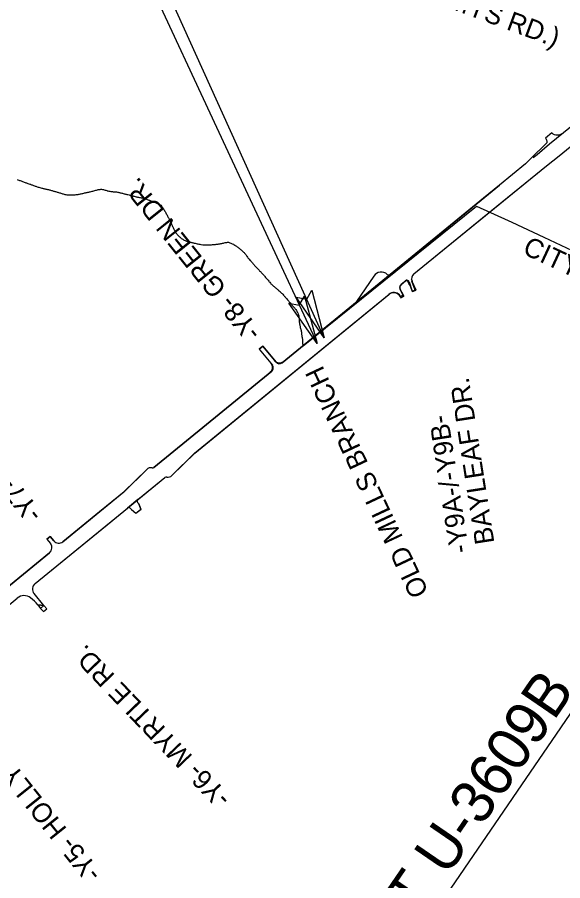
# Model space of a CAD drawing. Extents: x 2312641 to 2338852, y 590461 to 618614.
# Drawn here: x 2323527 to 2326066, y 598163 to 602179 of the extents above; entities that cross this region are included whole.
import ezdxf

# ---------------------------------------------------------------- set-up
doc = ezdxf.new("R2010")
doc.units = 0
for name, color, linetype in [('Default', 7, 'Continuous'), ('Default Symbol CELL', 7, 'Continuous'), ('Exist Property Monument CELL', 7, 'Continuous'), ('Exist Structure Minor Head and End Wall Leader', 7, 'Continuous'), ('Exist Structure Minor Pipes RCP 15 Inch Text', 7, 'Continuous')]:
    doc.layers.add(name, color=color, linetype=linetype)

msp = doc.modelspace()

# ---------------------------------------------------------------- linework, layer by layer
at = {"layer": 'Default'}
for points in [[(2323526.2, 601424.9), (2323530, 601423.4), (2323534, 601421.8), (2323537.8, 601420.4), (2323541, 601419.1), (2323544.8, 601417.6), (2323548.5, 601416.2), (2323552, 601414.9), (2323556, 601413.4), (2323559.8, 601412.1), (2323563.5, 601410.7), (2323567.2, 601409.3), (2323570.2, 601408.3), (2323573, 601407.3), (2323576.8, 601405.9), (2323580.5, 601404.6), (2323584.8, 601403.1), (2323588, 601401.9), (2323591, 601400.9), (2323593.8, 601399.9), (2323596.5, 601398.9), (2323599.5, 601397.8), (2323602.2, 601396.8), (2323607, 601395.2), (2323610.8, 601393.9), (2323613.5, 601392.9), (2323616.5, 601391.9), (2323619.5, 601390.9), (2323624, 601389.4), (2323627.8, 601388.2), (2323631.8, 601387.1), (2323636.2, 601385.8), (2323641.2, 601384.4), (2323644.2, 601383.7), (2323647, 601382.9), (2323650, 601382.2), (2323653.8, 601381.2), (2323656.8, 601380.6), (2323660.8, 601379.8), (2323664.5, 601378.9), (2323668, 601378.2), (2323672, 601377.3), (2323675.2, 601376.5), (2323678.2, 601375.8), (2323682.2, 601374.9), (2323686, 601373.9), (2323689, 601372.9), (2323692.8, 601371.8), (2323695.5, 601370.8), (2323699.2, 601369.6), (2323702.2, 601368.8), (2323705.5, 601367.8), (2323709, 601366.8), (2323712.8, 601365.8), (2323716.5, 601364.7), (2323719.5, 601363.8), (2323723.2, 601362.6), (2323726.2, 601361.7), (2323730, 601360.4), (2323733.8, 601359.2), (2323737.5, 601357.9), (2323740.5, 601357), (2323745.2, 601355.9), (2323749.2, 601355.1), (2323753, 601354.3), (2323757.5, 601353.6), (2323760.5, 601353.3), (2323765, 601353), (2323768, 601352.8), (2323769.5, 601352.6), (2323773, 601352.7), (2323777.5, 601352.5), (2323780.5, 601352.6), (2323785, 601352.9)], [(2323785, 601352.9), (2323789, 601353.1), (2323793, 601353.4), (2323796.2, 601353.6), (2323801, 601354.2), (2323810, 601355.3), (2323813.5, 601355.9), (2323816.8, 601356.4), (2323820.8, 601357.2), (2323824.5, 601358.1), (2323828.5, 601358.9), (2323831.5, 601359.6), (2323836.2, 601360.8), (2323840.2, 601361.6), (2323844, 601362.6), (2323848.5, 601363.6), (2323852, 601364.2), (2323856, 601364.9), (2323859.8, 601365.7), (2323863.8, 601366.4), (2323867, 601367.1), (2323871.5, 601368.4), (2323875.2, 601369.4), (2323879.2, 601370.6), (2323883.5, 601371.8), (2323888.8, 601373.3), (2323892.8, 601374.4), (2323896.5, 601375.4), (2323901, 601376.6), (2323904.2, 601377.2), (2323908.2, 601377.9), (2323912.2, 601378.5), (2323916.2, 601379), (2323919.2, 601379.2), (2323924, 601378.3), (2323928, 601377.4), (2323931.8, 601376.4), (2323936.5, 601375.1), (2323939.5, 601374.1), (2323943.2, 601373), (2323946.2, 601372.2), (2323949, 601371.4), (2323953.8, 601370.3), (2323958.5, 601369.6), (2323962.2, 601369), (2323966.2, 601368.5), (2323970.8, 601367.9), (2323974.2, 601367.7), (2323982.2, 601367.2), (2323986.2, 601366.8), (2323989.2, 601366.5), (2323993.2, 601365.8), (2323996, 601365.2), (2324000, 601364.4), (2324003, 601363.7), (2324006.2, 601362.9), (2324009.8, 601362), (2324013.5, 601361), (2324016.5, 601360.2), (2324019.2, 601359.4), (2324024, 601358.2), (2324028, 601357.2), (2324031, 601356.5), (2324034, 601355.8), (2324036.8, 601355), (2324041.5, 601353.8), (2324047.5, 601352.3), (2324051.2, 601351.3), (2324054.2, 601350.6), (2324058.5, 601349.5), (2324062, 601348.7), (2324066, 601347.7), (2324068.8, 601347), (2324071.8, 601346.3), (2324076, 601345.2), (2324080, 601344.4), (2324083.5, 601343.6), (2324087.2, 601342.8), (2324091.2, 601341.9), (2324095.5, 601341), (2324099, 601340.2), (2324103, 601339.3), (2324106.8, 601338.4), (2324111.2, 601337.4), (2324116.5, 601336.1), (2324120.5, 601335), (2324124.2, 601333.9), (2324128.8, 601332.7), (2324132, 601331.6), (2324135.8, 601330.1), (2324139.2, 601328.7), (2324142.2, 601327.5), (2324145.8, 601326.1), (2324148.5, 601324.9), (2324152.2, 601323.5), (2324156, 601322.1), (2324159, 601321.2)], [(2324159, 601321.2), (2324162.8, 601320), (2324165.5, 601319), (2324169.2, 601317.5), (2324173, 601316.1), (2324175.8, 601314.9), (2324178, 601314.1), (2324182.2, 601311.9), (2324185.8, 601310), (2324189, 601308.7), (2324190.2, 601307.5), (2324194.8, 601304.3), (2324198.2, 601300.5), (2324200.8, 601297.4), (2324203.2, 601294.3), (2324205.8, 601290.7), (2324208.2, 601286.6), (2324210.8, 601282.5), (2324212.8, 601279.1), (2324215, 601275.2), (2324216.8, 601272.1), (2324218.5, 601268.6), (2324220.5, 601265.1), (2324222.8, 601260.8), (2324224.2, 601258), (2324226, 601254.4), (2324227.8, 601250.9), (2324230, 601247.5), (2324232.2, 601243.8), (2324234.8, 601238.8), (2324236.8, 601235.2), (2324239.2, 601230), (2324241, 601226.8), (2324242.2, 601224), (2324243.5, 601220.9), (2324245.2, 601217.2), (2324247, 601212.8), (2324248.2, 601209.9), (2324250, 601206.2), (2324251.2, 601203.4), (2324252.2, 601200.7), (2324254, 601197.1), (2324255.5, 601193.8), (2324257, 601190.7), (2324258.2, 601187.9), (2324260, 601184.4), (2324261.8, 601180.8), (2324263.2, 601178), (2324266.2, 601174.3), (2324269, 601171.3), (2324271.8, 601168.4), (2324274.2, 601165.6), (2324277, 601162.7), (2324279.2, 601160.4), (2324281.5, 601158.3), (2324284.5, 601155.6), (2324287.8, 601152.3), (2324290.5, 601150.4), (2324293.8, 601148.2), (2324297.2, 601146.1), (2324300.5, 601144), (2324303.5, 601142.4), (2324307.8, 601140.7), (2324311.5, 601139.3), (2324315.2, 601138.1), (2324319.5, 601136.7), (2324323, 601135.6), (2324326.8, 601134.5), (2324329.8, 601133.6), (2324334.5, 601132.2), (2324337.5, 601131.4), (2324340.5, 601130.8), (2324344.2, 601130.1), (2324347.2, 601129.4), (2324350, 601128.8), (2324355.8, 601127.6), (2324359.8, 601126.4), (2324363.8, 601125.4), (2324367.5, 601124.4), (2324372.2, 601123.4), (2324377.5, 601122.8), (2324381.2, 601122.3), (2324390.2, 601121.2), (2324393.2, 601120.9), (2324405.2, 601120.2), (2324408.2, 601120.1), (2324413.2, 601120.2), (2324417.2, 601120.4), (2324420.2, 601120.6), (2324424, 601120.8), (2324427, 601120.9), (2324431.2, 601121.2), (2324435.2, 601121.5), (2324438.2, 601121.8), (2324441.2, 601121.9), (2324444.8, 601122.2), (2324449.2, 601122.7)], [(2324752.5, 600900.8), (2324754.5, 600898.8), (2324757.2, 600896.2), (2324759.8, 600893.9), (2324762.8, 600890.4), (2324766, 600886.8), (2324769.5, 600882.9), (2324771.5, 600880.6), (2324773.2, 600878.4), (2324776, 600875.4), (2324778.5, 600872.4), (2324781.8, 600868.8), (2324784.8, 600865.4), (2324787.8, 600861.9), (2324790.5, 600858.8), (2324793, 600855.8), (2324795.8, 600852.4), (2324797.8, 600850), (2324800.5, 600846.4), (2324803, 600843.2), (2324805.2, 600840.1), (2324807.2, 600837.6), (2324810.2, 600834.7), (2324813.2, 600831.9), (2324816, 600829.1), (2324818.5, 600826.6), (2324821.2, 600823.2), (2324823.8, 600820), (2324826.8, 600815.4), (2324828.8, 600811.4), (2324830.5, 600807.9), (2324832.2, 600804.2), (2324834.5, 600798.6), (2324835.8, 600794.8), (2324837, 600790.2), (2324837.8, 600787.1), (2324838.2, 600783.2), (2324838.8, 600778), (2324839, 600773.2), (2324839, 600769.2), (2324839.2, 600765.2), (2324839.5, 600761.8), (2324840.2, 600757.3), (2324841, 600753.4), (2324842, 600749), (2324842.5, 600745.6), (2324843.2, 600742.6), (2324843.8, 600739.6), (2324844.5, 600735.5), (2324845.5, 600732), (2324846.5, 600729), (2324847.5, 600726.2), (2324848.8, 600721.8), (2324849, 600718.4), (2324849.5, 600713.6), (2324849.8, 600710.4), (2324850, 600706.9), (2324850.5, 600704), (2324850.8, 600700.5), (2324851.2, 600696.5), (2324851.8, 600693.6), (2324852.8, 600689.7), (2324853.2, 600686.8), (2324854, 600683.8), (2324854.8, 600680.1), (2324854.8, 600676.9), (2324854.5, 600672.9), (2324854.5, 600668.9), (2324854.2, 600665.4), (2324855, 600661), (2324855.5, 600657.3), (2324857, 600654.8), (2324858.5, 600651.2), (2325664.2, 601300), (2325730.2, 601270.9), (2325828.2, 601225.3), (2325978.2, 601155.4), (2326135.5, 601082.1)], [(2324449.2, 601122.7), (2324453.2, 601123.1), (2324457.2, 601123.5), (2324461.8, 601124.1)], [(2324461.8, 601124.1), (2324465, 601124.6), (2324468, 601125), (2324471, 601125.5), (2324475, 601126.2), (2324479.5, 601127), (2324482.8, 601127.8), (2324486.8, 601128.8), (2324490.5, 601129.8), (2324494.5, 601130.7), (2324497.8, 601131.5), (2324502.2, 601131.7), (2324505.8, 601132.2), (2324510, 601133), (2324514, 601131), (2324516.8, 601130.4), (2324521.2, 601128.4), (2324524.8, 601126.8), (2324527.8, 601125.6), (2324533, 601123.1), (2324535.5, 601121.4), (2324539, 601119.2), (2324541.5, 601117.6), (2324544, 601115.9), (2324547.5, 601113.5), (2324550.5, 601111.4), (2324553.8, 601109.1), (2324557, 601106.7), (2324559.2, 601104.9), (2324562.8, 601102.3), (2324566.2, 601099.2), (2324568.5, 601097.2), (2324570.8, 601095.2), (2324573.8, 601092.6), (2324576, 601090.6), (2324579.5, 601087.1), (2324582.5, 601084.2), (2324584.2, 601081.9), (2324587, 601080), (2324589.2, 601077.7), (2324591.2, 601074.8), (2324592.8, 601072.2), (2324594.2, 601069.6), (2324596, 601067), (2324598.5, 601062.8), (2324600.5, 601060.5), (2324603, 601057.5), (2324606, 601054), (2324610, 601049.6), (2324612.2, 601046.9), (2324614.2, 601044.7), (2324616.2, 601042.4), (2324618.8, 601039.3), (2324621.5, 601036.1), (2324624, 601033.2), (2324626.5, 601030.1), (2324629, 601027), (2324631.2, 601024.3), (2324633.2, 601022.1), (2324635.8, 601019.2), (2324639.8, 601015.1), (2324643, 601011.4), (2324646, 601008.4), (2324649.5, 601005), (2324652.2, 601002.2), (2324654.8, 600999.7), (2324658.5, 600996.1), (2324661.5, 600992.9), (2324664.2, 600990.1), (2324666.2, 600987.9), (2324668.8, 600985.2), (2324671.2, 600982.4), (2324674.2, 600979.1), (2324677, 600976.1), (2324679.8, 600973.1), (2324683.2, 600969.2), (2324686.2, 600965.6), (2324689, 600962.6), (2324691.5, 600959.6), (2324694.5, 600955.9), (2324697.8, 600951.8), (2324700.2, 600948.7), (2324702.2, 600946.5), (2324705.5, 600942), (2324708, 600939.4), (2324711, 600936.9), (2324714, 600934.2), (2324716.8, 600931.4), (2324719.2, 600929), (2324722.8, 600926), (2324725.8, 600923.4), (2324728.8, 600920.8), (2324731.8, 600918.2), (2324735, 600915.7), (2324738, 600913.2), (2324741.2, 600910.7), (2324743.5, 600908.8), (2324746.8, 600906.1), (2324750.2, 600902.8), (2324752.5, 600900.8)]]:
    msp.add_lwpolyline(points, dxfattribs=at)
at = {"layer": 'Default Symbol CELL'}
for p, q in [((2326003.7, 601589.6), (2326394.4, 601908.6)), ((2326048.6, 601534.6), (2326503.2, 601905.7)), ((2325946.4, 601541.2), (2326003.7, 601589.6)), ((2325927.6, 601525.9), (2325946.4, 601541.2)), ((2325989.7, 601488.2), (2326048.6, 601534.6)), ((2325373.5, 600985), (2325989.7, 601488.2)), ((2324759.5, 600572.2), (2325771.6, 601398.5)), ((2325312.2, 600935), (2325334.6, 600953.3)), ((2325350.4, 600948.9), (2325365.8, 600904.7)), ((2325379, 600909.3), (2325364.1, 600951.9)), ((2325308.4, 600916.4), (2325326.8, 600881.6)), ((2325365.8, 600904.7), (2325379, 600909.3)), ((2324352.9, 600151.9), (2325256.9, 600889.9)), ((2325310, 600879.1), (2325312.7, 600874.1)), ((2325312.7, 600874.1), (2325326.8, 600881.6)), ((2324653.6, 600635.2), (2324670.6, 600649.1)), ((2324653.6, 600635.2), (2324714.3, 600561.2)), ((2324670.6, 600649.1), (2324731.4, 600575)), ((2324163, 600085.2), (2324711.4, 600533)), ((2324247, 600047.8), (2324352.9, 600151.9)), ((2324130.1, 600076), (2324023.8, 599971.6)), ((2324088.9, 599936.3), (2324214.2, 600038.6)), ((2323739.4, 599739.4), (2324023.8, 599971.6)), ((2324087.2, 599922.6), (2324092.2, 599915.9)), ((2324092.2, 599915.9), (2324102.6, 599891.1)), ((2323609.9, 599545.3), (2324039.5, 599896)), ((2324052.7, 599895.6), (2324059.5, 599889.2)), ((2324059.5, 599889.2), (2324079.5, 599872.2)), ((2324079.2, 599872), (2324103.2, 599891.6)), ((2323665.4, 599751), (2323680.9, 599763.6)), ((2323665.4, 599751), (2323681.7, 599731)), ((2323680.9, 599763.6), (2323697.2, 599743.7)), ((2323030.9, 599161), (2323677.4, 599688.8)), ((2323651.3, 599442.6), (2323605.2, 599498.8)), ((2323622.2, 599446.5), (2323635.9, 599429.9)), ((2323651.3, 599442.6), (2323635.9, 599429.9))]:
    msp.add_line(p, q, dxfattribs=at)
for centre, radius, start, end in [((2325340.9, 600945.6), 10, 19.2579, 129.228), ((2325392.4, 600961.8), 30, 129.228, 199.2579), ((2325321.7, 600923.4), 15, 129.228, 207.8225), ((2325279.1, 600862.8), 35, 27.8225, 129.228), ((2324698.8, 600548.5), 20, 309.228, 39.3225), ((2324746.8, 600587.7), 20, 219.3225, 309.228), ((2324149, 600056.7), 27, 78.1586, 134.5091), ((2324156.6, 600093), 10, 258.1586, 309.228), ((2324220.5, 600030.8), 10, 78.1586, 129.228), ((2324228.1, 600067.1), 27, 258.1586, 314.5091), ((2324095.2, 599928.6), 10, 129.228, 216.809), ((2324045.8, 599888.3), 10, 46.993, 129.228), ((2323720.4, 599762.6), 30, 219.228, 309.228), ((2323658.4, 599712), 30, 309.228, 39.228), ((2323630.8, 599519.7), 33, 129.228, 219.3566), ((2323558.7, 599438.9), 50, 52.6181, 129.228), ((2323467.6, 599319.7), 200, 39.3566, 52.6181)]:
    msp.add_arc(centre, radius, start, end, dxfattribs=at)
at = {"layer": 'Exist Property Monument CELL'}
for p, q in [((2326048.6, 601534.6), (2326484.6, 601890.5)), ((2326014.5, 601641), (2325985.3, 601617.2)), ((2325990.1, 601592.9), (2325919.6, 601523.8)), ((2325985.3, 601617.2), (2325985.9, 601616.6)), ((2325919.6, 601523.8), (2325893, 601497.6)), ((2325989.7, 601488.2), (2326048.6, 601534.6)), ((2325734, 601279.4), (2325989.7, 601488.2)), ((2325696.5, 601337.2), (2324759.5, 600572.2)), ((2325373.5, 600985), (2325734, 601279.4)), ((2325104.6, 600854), (2325262.3, 600982.7)), ((2325186.6, 600975), (2325106.6, 600856.2)), ((2325314.6, 600937), (2325336.3, 600954.7)), ((2325334.6, 600953.3), (2325331.8, 600951)), ((2325336.3, 600954.7), (2325334.6, 600953.3)), ((2325338.6, 600955.8), (2325338.8, 600955.7)), ((2325338.8, 600955.7), (2325339.2, 600955.4)), ((2325341.2, 600953.9), (2325339.2, 600955.4)), ((2325343.3, 600951.8), (2325341.2, 600953.9)), ((2325363.8, 600955.7), (2325362.6, 600958.5)), ((2325364.1, 600951.9), (2325379, 600909.3)), ((2325379, 600909.3), (2325364.1, 600951.9)), ((2325383.5, 600909.9), (2325365.7, 600950.2)), ((2325309.6, 600912.2), (2325323.2, 600886.3)), ((2325323.2, 600886.3), (2325309.6, 600912.2)), ((2325365.7, 600904.7), (2325379, 600909.3)), ((2325379, 600909.3), (2325366.1, 600904.9)), ((2325367.2, 600902.7), (2325383.5, 600909.9)), ((2324352.7, 600151.7), (2325257.7, 600890.6)), ((2325257.7, 600890.6), (2325256.9, 600889.9)), ((2325305.4, 600887.4), (2325307.9, 600882.7)), ((2325307.9, 600882.7), (2325305.4, 600887.4)), ((2325310, 600879.1), (2325312.7, 600874.1)), ((2325323.2, 600886.3), (2325310.8, 600879.8)), ((2325310.8, 600879.8), (2325323.2, 600886.3)), ((2325312.7, 600874.1), (2325326.8, 600881.6)), ((2325326.8, 600881.6), (2325321.4, 600891.9)), ((2325366.1, 600904.9), (2325367.2, 600902.7)), ((2324670.6, 600649.1), (2324653.6, 600635.2)), ((2324653.6, 600635.2), (2324714.3, 600561.2)), ((2324731.4, 600575), (2324670.6, 600649.1)), ((2324714.3, 600561.2), (2324707.9, 600568.9)), ((2324725, 600582.8), (2324731.4, 600575)), ((2324759.5, 600572.2), (2324767.2, 600578.5)), ((2324711.4, 600533), (2324163, 600085.2)), ((2324703.7, 600526.7), (2324711.4, 600533)), ((2324247, 600047.8), (2324352.7, 600151.7)), ((2324130.1, 600076), (2324024.8, 599972.5)), ((2323945.2, 599819), (2324214.2, 600038.6)), ((2324024.1, 599971.9), (2323909.8, 599878.5)), ((2324088.9, 599936.3), (2324039.5, 599896)), ((2324092.2, 599915.9), (2324087.2, 599922.6)), ((2324102.6, 599891.1), (2324092.2, 599915.9)), ((2323909.8, 599878.5), (2323739.4, 599739.4)), ((2324052.7, 599895.6), (2324059.5, 599889.2)), ((2324059.5, 599889.2), (2324079.5, 599872.2)), ((2324079.5, 599872.2), (2324102.6, 599891.1)), ((2323609.9, 599545.3), (2323945.2, 599819)), ((2323680.9, 599763.6), (2323665.4, 599751)), ((2323665.4, 599751), (2323681.7, 599731)), ((2323697.2, 599743.7), (2323680.9, 599763.6)), ((2323677.4, 599688.8), (2323030.9, 599161)), ((2323178.7, 599193.2), (2323527, 599477.6)), ((2323651.3, 599442.6), (2323605.2, 599498.8)), ((2323651.3, 599442.6), (2323622.2, 599446.5)), ((2323622.2, 599446.5), (2323635.9, 599429.9)), ((2323622.2, 599446.5), (2323651.3, 599442.6)), ((2323635.9, 599429.9), (2323651.3, 599442.6)), ((2323651.3, 599442.6), (2323635.9, 599429.9)), ((2323635.9, 599429.9), (2323648.5, 599414.5)), ((2323648.5, 599414.5), (2323664, 599427.1)), ((2323664, 599427.1), (2323651.3, 599442.6))]:
    msp.add_line(p, q, dxfattribs=at)
for points in [[(2325893, 601497.6), (2325771.6, 601398.5), (2325696.5, 601337.2)], [(2325339.2, 600955.4), (2325338.8, 600955.7), (2325338.6, 600955.8)], [(2325339.2, 600955.4), (2325341.2, 600953.9), (2325343.3, 600951.8)], [(2325321.4, 600891.9), (2325311.1, 600910.8), (2325307.7, 600917.2)]]:
    msp.add_lwpolyline(points, dxfattribs=at)
for centre, radius, start, end in [((2326040.6, 601671.3), 40, 229.3066, 309.2278), ((2325961.5, 601595.8), 32, 10.9869, 40.323), ((2325983.1, 601600), 10, 314.4775, 10.9869), ((2325221.5, 600951.6), 42, 48.3568, 146.1555), ((2325256, 600990.5), 10, 228.3568, 309.228), ((2325338.1, 600943.3), 10, 58.5415, 129.228), ((2325340.9, 600945.6), 10, 100.1034, 129.228), ((2325340.9, 600945.6), 10, 100.1034, 129.228), ((2325339.5, 600950.8), 5, 99.7805, 129.228), ((2325339.5, 600950.8), 5, 28.0047, 129.228), ((2325339.5, 600950.8), 5, 70.0679, 99.7805), ((2325340.9, 600945.6), 10, 88.3688, 100.1034), ((2325340.9, 600945.6), 10, 88.3688, 100.1034), ((2325339.5, 600950.8), 5, 28.0047, 70.0679), ((2325338.1, 600943.3), 10, 40.6638, 58.5415), ((2324990.7, 600765.4), 400, 27.4527, 28.0047), ((2324990.7, 600765.4), 400, 20.3835, 28.0047), ((2325392.4, 600961.8), 30, 129.228, 199.2579), ((2325392.4, 600961.8), 30, 186.3702, 199.2579), ((2325393.1, 600962.3), 30, 192.7842, 203.8439), ((2325327.3, 600921.5), 20, 129.228, 207.8225), ((2325327.3, 600921.5), 20, 192.4991, 207.8225), ((2325279.1, 600862.8), 35, 34.6748, 129.228), ((2325279.9, 600863.4), 35, 43.1814, 129.228), ((2325279.9, 600863.4), 35, 27.8225, 129.228), ((2325279.9, 600863.4), 35, 27.8225, 43.1814), ((2325279.1, 600862.8), 35, 27.8225, 34.6748), ((2325098.3, 600861.7), 10, 309.2329, 326.1555), ((2324684.7, 600549.9), 30, 309.228, 39.3225), ((2324698.8, 600548.5), 20, 309.228, 39.3225), ((2324698.8, 600548.5), 20, 309.228, 39.3225), ((2324748.2, 600601.8), 30, 219.3225, 309.228), ((2324746.8, 600587.7), 20, 219.3225, 309.228), ((2324746.8, 600587.7), 20, 219.3225, 309.228), ((2324149, 600056.7), 27, 78.1586, 134.5091), ((2324156.6, 600093), 10, 258.1586, 309.228), ((2324220.5, 600030.8), 10, 78.1586, 129.228), ((2324228.1, 600067.1), 27, 258.1586, 314.5091), ((2324017.8, 599979.6), 10, 309.228, 314.5091), ((2324095.2, 599928.6), 10, 129.228, 216.809), ((2324045.8, 599888.3), 10, 46.993, 129.228), ((2323720.4, 599762.6), 30, 219.228, 309.228), ((2323658.4, 599712), 30, 309.228, 39.228), ((2323630.8, 599519.7), 33, 129.228, 219.3566), ((2323558.7, 599438.9), 50, 52.6181, 129.228), ((2323467.6, 599319.7), 200, 39.3566, 52.6181)]:
    msp.add_arc(centre, radius, start, end, dxfattribs=at)
at = {"layer": 'Exist Structure Minor Head and End Wall Leader'}
for points in [[(2324898.1, 600909.1), (2324955.6, 600688.1), (2324825.9, 600877.7), (2324874.2, 600868)], [(2324863.2, 600881.9), (2324923.1, 600661.6), (2324791.3, 600849.8), (2324839.7, 600840.6)]]:
    msp.add_lwpolyline(points, close=True, dxfattribs=at)
at = {"layer": 'Exist Structure Minor Pipes RCP 15 Inch Text'}
for p, q in [((2323961.5, 602725.8), (2324923.1, 600661.6)), ((2324955.6, 600688.1), (2324234.7, 602280.3)), ((2326387.6, 599359.5), (2323924, 595764.7))]:
    msp.add_line(p, q, dxfattribs=at)

# ---------------------------------------------------------------- texts
at = {"layer": 'Default'}
msp.add_text('CITY OF GOLDSBORO', height=90, rotation=335.0248, dxfattribs=at).set_placement((2325874.1, 601081.1))
at = {"layer": 'Exist Structure Minor Pipes RCP 15 Inch Text'}
for s, height, rotation, p in [('(TOMMYS RD.)', 90, 339.6814, (2325235, 602332.9)), ('-Y8- GREEN DR.', 90, 128.6934, (2324668.3, 600715.9)), ('-Y7- OAKHILL RD.', 90, 128.6934, (2323649.2, 599871.4)), ('OLD MILLS BRANCH', 90, 115.171, (2325443.3, 599505.2)), ('BAYLEAF DR.', 90, 98.8574, (2325748.2, 599734.7)), ('-Y9A-/-Y9B-', 90, 98.8574, (2325630.4, 599692.9)), ('-Y6- MYRTLE RD.', 90, 133.7488, (2324527.3, 598552.8)), ('BEGIN TIP PROJECT U-3609B', 200, 55.5761, (2323990.8, 595936.5)), ('-Y5- HOLLY RD.', 90, 128.6934, (2323924.4, 598199.7))]:
    msp.add_text(s, height=height, rotation=rotation, dxfattribs=at).set_placement(p)

doc.saveas('drawing.dxf')
